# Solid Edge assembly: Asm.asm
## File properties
Author: Deepak Maini
Template: Normal.asm
Last saved by: MYPC
Revision: 7
Application: Solid Edge
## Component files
endplatemod.par
bolt.par
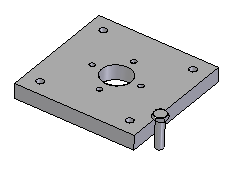
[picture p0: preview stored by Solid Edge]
